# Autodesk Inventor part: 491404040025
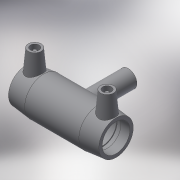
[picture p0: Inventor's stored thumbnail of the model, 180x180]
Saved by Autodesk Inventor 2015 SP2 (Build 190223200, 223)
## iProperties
Created: 2017-06
Part Number: 491404040025
Material: Generic
Description: PLASSON REDUCING TEE 40x25x40
Document SubType Name: Modeling
Designer: KIM
Mass: 57.3761 g
Surface Area: 241.06 cm^2
Volume: 57.3761 cm^3
Density: 1 g/cm^3
Appearance: Default
Author: KIM
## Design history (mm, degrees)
derived "491404.ipt"
feature "Solid1::491404.ipt"
tag "TaggingFeature1"
body "Solid1"
other parameters: "d2" = 56, "d3" = 43, "d4" = 24, "d5" = 50.4, "d6" = 38, "d8" = 168 deg, "d10" = 17.2, "d11" = 5.73333, "d14" = 17.6296, "d17" = 36, "d19" = 3.52592, "d20" = 168 deg, "d22" = 52.08, "d23" = 56, "d25" = 135 deg, "d26" = 84, "d29" = 47, "d30" = 15, "d31" = 48, "d34" = 5 deg, "d35" = 15, "d39" = 5 deg, "d41" = 4, "d42" = 14, "d43" = 0, "d45" = 4, "d46" = 6, "d47" = 0, "d48" = -72, "d49" = 25, "d51" = 0, "d54" = 0, "d55" = 50.4, "d56" = 56, "d57" = 42, "d58" = 135 deg, "d59" = 43, "d60" = 43, "d61" = 135 deg, "d62" = 72, "d72" = 54.6, "d73" = 27.3, "d74" = -72, "d75" = 26.25, "d77" = 0, "d80" = 0, "d81" = 25, "d82" = 44, "d83" = 0, "d84" = 3, "d85" = 0, "d86" = 14.33333, "d87" = 51.0384, "d88" = 5.73333, "d89" = 3, "d90" = 0, "L_1" = 43, "D_" = 56, "A_" = 47, "d_2" = 12, "H_" = 72, "d_1" = 25
